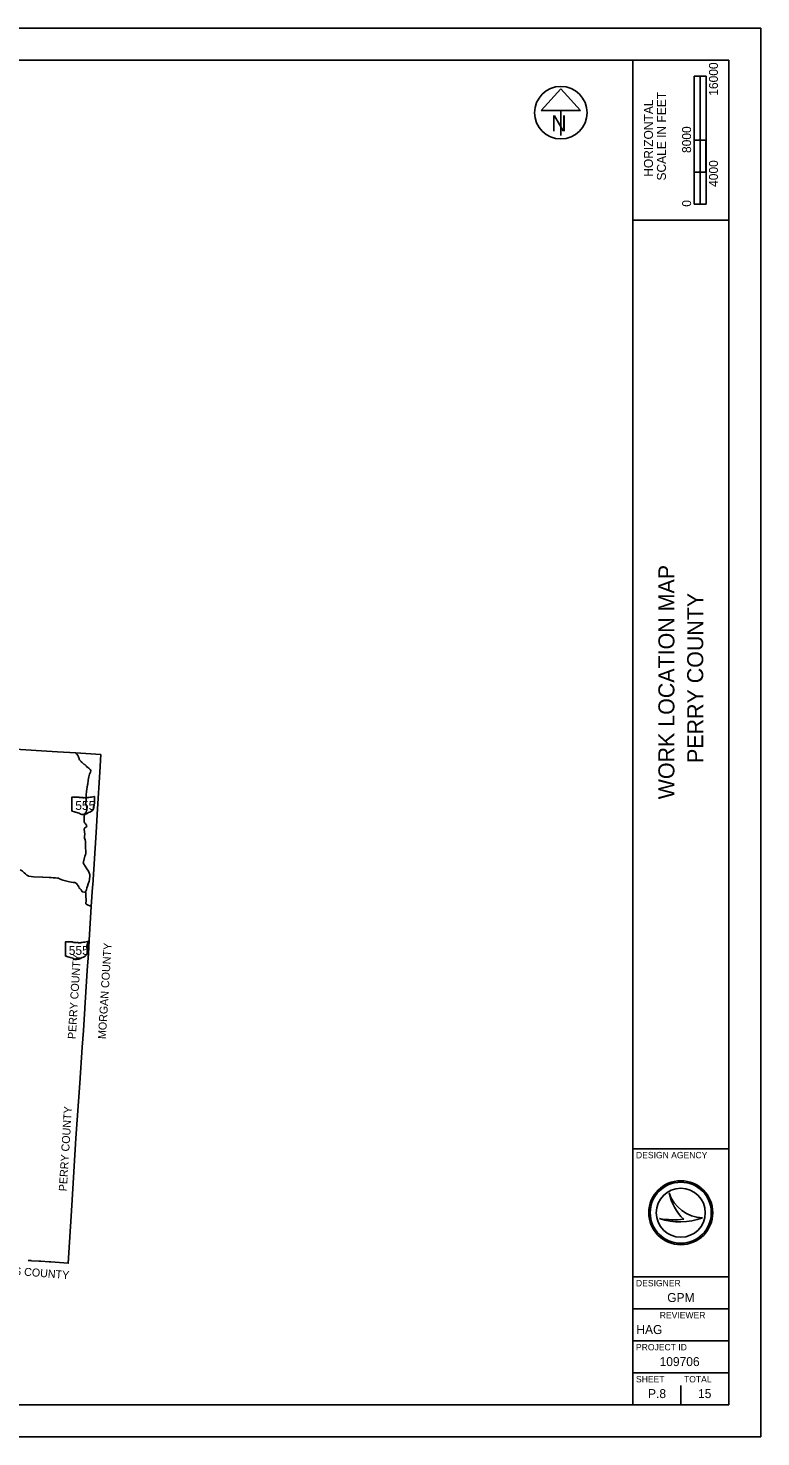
# Model space of a CAD drawing. Extents: x 1912787 to 2184787, y 543251 to 719251.
# Drawn here: x 2093246 to 2184787, y 543251 to 719251 of the extents above; entities that cross this region are included whole.
import ezdxf

# ---------------------------------------------------------------- set-up
doc = ezdxf.new("R2010")
doc.units = 0
for name, color, linetype in [('GM_X_County', 7, 'Continuous'), ('GM_X_County_Text', 7, 'Continuous'), ('GM_X_State_Location', 7, 'Continuous'), ('GM_X_State_Route', 7, 'Continuous'), ('GM_X_State_Shield', 7, 'Continuous'), ('SH_Border', 7, 'Continuous'), ('SH_Cut_Line', 7, 'Continuous'), ('SH_Data', 7, 'Continuous'), ('SH_Masking', 7, 'Continuous'), ('SH_Text', 7, 'Continuous')]:
    doc.layers.add(name, color=color, linetype=linetype)

msp = doc.modelspace()

# ---------------------------------------------------------------- linework, layer by layer
at = {"layer": 'GM_X_County'}
msp.add_lwpolyline([(2090938, 629224), (2096895, 628847), (2099187, 628710), (2102312, 628487), (2102193, 626283), (2101908, 621725), (2101721, 618763), (2101311, 612237), (2101290, 611908), (2101137, 609504), (2100881, 605294), (2100816, 604427), (2100776, 603648), (2100631, 601508), (2100343, 596816), (2100327, 596770), (2100147, 594037), (2099987, 591925), (2099681, 587430), (2099218, 580571), (2098707, 572170), (2098250, 564948), (2096075, 565106), (2095873, 565126), (2094827, 565192), (2094797, 565200), (2094779, 565204), (2094764, 565207), (2094750, 565209), (2094740, 565211), (2094727, 565212), (2094716, 565212), (2094701, 565213), (2094683, 565212), (2094668, 565211), (2094648, 565210), (2094631, 565207), (2094613, 565204), (2093651, 565260), (2093610, 565267), (2093571, 565272), (2093538, 565275), (2093505, 565278), (2093473, 565281), (2093444, 565283), (2093421, 565284), (2093383, 565286), (2093357, 565287), (2093335, 565287), (2093279, 565284), (2093242, 565282)], dxfattribs=at)
at = {"layer": 'GM_X_State_Route'}
for points in [[(2099600, 627994), (2099570, 628077), (2099522, 628214), (2099451, 628392), (2099374, 628518), (2099298, 628605), (2099188, 628707)], [(2101076, 626465), (2101081, 626479), (2101088, 626513), (2100994, 626609), (2100806, 626799), (2100700, 626898), (2100545, 626998), (2100502, 627052), (2100472, 627100), (2100453, 627131), (2100427, 627169), (2100408, 627187), (2100370, 627213), (2100312, 627242), (2100254, 627266), (2100196, 627297), (2100151, 627330), (2100111, 627364), (2099976, 627498), (2099922, 627559), (2099883, 627610), (2099831, 627677), (2099793, 627720), (2099748, 627765), (2099661, 627851), (2099626, 627921), (2099600, 627994)], [(2100572, 621814), (2100571, 621851), (2100568, 621979), (2100564, 622050), (2100492, 622189), (2100433, 622306), (2100418, 622362), (2100421, 622417), (2100438, 622470), (2100450, 622524), (2100481, 622839), (2100512, 623284), (2100512, 623462), (2100543, 623875), (2100669, 624702), (2100686, 624812), (2100760, 625292), (2100818, 625708), (2100851, 625884), (2100904, 626052), (2101021, 626309), (2101076, 626465)], [(2100227, 620259), (2100227, 620264), (2100229, 620349), (2100237, 620530), (2100238, 620563), (2100243, 620639), (2100243, 620701), (2100248, 620763), (2100256, 620821), (2100264, 620861), (2100289, 620950), (2100298, 620979), (2100310, 621008), (2100324, 621040), (2100336, 621063), (2100346, 621082), (2100374, 621129), (2100438, 621236), (2100484, 621313), (2100499, 621347), (2100508, 621372), (2100524, 621411), (2100538, 621450), (2100548, 621475), (2100552, 621492), (2100557, 621524), (2100560, 621544), (2100562, 621562), (2100566, 621601), (2100569, 621651), (2100569, 621699), (2100573, 621771), (2100572, 621814)], [(2100408, 611276), (2100464, 611414), (2100522, 611579), (2100591, 611844), (2100652, 612054), (2100742, 612343), (2100851, 612691), (2100894, 612858), (2100934, 613401), (2100932, 613525), (2100914, 613602), (2100870, 613699), (2100765, 613917), (2100585, 614226), (2100150, 614888), (2100131, 614961), (2100158, 615103), (2100330, 615799), (2100339, 615853), (2100350, 615895), (2100407, 616002), (2100438, 616062), (2100460, 616142), (2100427, 617136), (2100421, 617330), (2100428, 617496), (2100415, 617625), (2100354, 617832), (2100302, 618054), (2100274, 618180), (2100298, 618326), (2100309, 618521), (2100282, 618858), (2100241, 619116), (2100244, 619190), (2100271, 619254), (2100323, 619321), (2100558, 619494), (2100573, 619505), (2100586, 619514), (2100524, 619673), (2100407, 619847), (2100336, 619933), (2100281, 620014), (2100242, 620104), (2100237, 620123), (2100232, 620154), (2100228, 620186), (2100227, 620219), (2100227, 620259)], [(2092257, 614093), (2092407, 614019), (2092552, 613916), (2092757, 613724), (2092892, 613584), (2093069, 613433), (2093147, 613380), (2093234, 613338), (2093291, 613301), (2093344, 613282)], [(2093344, 613282), (2093921, 613233), (2095034, 613160)], [(2095034, 613160), (2095087, 613157), (2095851, 613117), (2096017, 613132), (2096109, 613128), (2096378, 613103), (2096525, 613096), (2096675, 613073), (2096929, 613058), (2097023, 613035), (2097154, 612983), (2097348, 612871), (2097595, 612783), (2098082, 612674), (2098421, 612602), (2098618, 612563), (2098871, 612516), (2099060, 612491), (2099171, 612457), (2099254, 612416), (2099326, 612338), (2099417, 612202), (2099470, 612148), (2099507, 612108), (2099565, 611968), (2099638, 611820), (2099691, 611762), (2099778, 611682), (2099849, 611607), (2099902, 611527), (2100011, 611349), (2100089, 611326), (2100275, 611300), (2100361, 611290), (2100408, 611276)], [(2100408, 611276), (2100432, 611248), (2100439, 611215), (2100444, 611101), (2100460, 610757), (2100484, 610316), (2100478, 610176), (2100465, 609961), (2100458, 609858), (2100465, 609825)], [(2100465, 609825), (2100485, 609797), (2100525, 609772), (2100578, 609761), (2100755, 609696), (2101138, 609501)], [(2100777, 603645), (2100702, 603918), (2100646, 604087), (2100602, 604252), (2100580, 604393), (2100579, 604512), (2100581, 604585), (2100597, 604681), (2100628, 604766), (2100667, 604862), (2100719, 604962), (2100882, 605291)]]:
    msp.add_lwpolyline(points, dxfattribs=at)
at = {"layer": 'GM_X_State_Shield'}
for p, q in [((2098713, 623153), (2098713, 621452)), ((2099561, 623182), (2098741, 623182)), ((2101515, 622334), (2101515, 623224)), ((2101515, 622334), (2101515, 622334)), ((2097900, 605048), (2097900, 603347)), ((2098748, 605077), (2097927, 605077)), ((2100701, 604230), (2100701, 605119)), ((2100701, 604230), (2100701, 604230))]:
    msp.add_line(p, q, dxfattribs=at)
for centre, major_axis, start_param, end_param in [((2098745, 623156), (32.5, 0), 1.7126934, 3.2834897), ((2099757, 623380), (315, 0), 4.042523, 4.731795), ((2099861, 622227), (1130, 0), 1.4047578, 1.6578581), ((2100118, 623165), (90.8, 0), 3.8360951, 5.1854146), ((2100251, 622969), (189, 0), 0.950623, 2.079405), ((2100495, 623238), (227, 0), 4.0815608, 5.1457227), ((2100896, 622662), (598, 0), 1.6990114, 2.1078141), ((2100517, 625501), (2971, 0), 4.8143942, 5.0423688), ((2101484, 623228), (31.2, 0), 6.1411519, 7.9890352), ((2098746, 621448), (32.7, 0), 3.00124, 4.5083009), ((2098751, 621622), (250, 0), 4.6659457, 4.8974612), ((2098802, 621353), (90.1, 0), 0.5192072, 1.6278991), ((2099939, 622882), (2146, 0), 4.1959971, 4.4889607), ((2100997, 620974), (407, 0), 1.6476453, 2.4884337), ((2100684, 621849), (743, 0), 5.1017525, 6.4400178), ((2101627, 621962), (211, 0), 2.3877238, 3.2625369), ((2101508, 622269), (48.3, 0), 1.8839779, 3.6710726), ((2101201, 622156), (290, 0), 5.9346948, 6.6959481), ((2101482, 622331), (33.4, 0), 5.05454, 6.4181714), ((2099300, 620687), (671, 0), 0.8235189, 1.3235874), ((2100026, 621345), (426, 0), 4.0264811, 4.9967352), ((2100272, 620757), (350, 0), 1.495662, 1.9409797), ((2100303, 621218), (227, 0), 4.6910439, 5.5073738), ((2100508, 621053), (63.9, 0), 1.1475842, 2.3151517), ((2100481, 621287), (240, 0), 4.9370686, 5.64225), ((2097932, 605052), (32.5, 0), 1.7126934, 3.2834897), ((2098943, 605275), (315, 0), 4.042523, 4.731795), ((2099047, 604122), (1130, 0), 1.4047578, 1.6578581), ((2099304, 605060), (90.8, 0), 3.8360951, 5.1854146), ((2099437, 604864), (189, 0), 0.950623, 2.079405), ((2099681, 605134), (227, 0), 4.0815608, 5.1457227), ((2100082, 604558), (598, 0), 1.6990114, 2.1078141), ((2099703, 607397), (2971, 0), 4.8143942, 5.0423688), ((2099870, 603744), (743, 0), 5.1017525, 6.4400178), ((2100813, 603857), (211, 0), 2.3877238, 3.2625369), ((2100694, 604164), (48.3, 0), 1.8839779, 3.6710726), ((2100387, 604052), (290, 0), 5.9346948, 6.6959481), ((2100670, 605123), (31.2, 0), 6.1411519, 7.9890352), ((2100668, 604226), (33.4, 0), 5.05454, 6.4181714), ((2097932, 603343), (32.7, 0), 3.00124, 4.5083009), ((2097937, 603517), (250, 0), 4.6659457, 4.8974612), ((2097988, 603249), (90.1, 0), 0.5192072, 1.6278991), ((2099126, 604777), (2146, 0), 4.1959971, 4.4889607), ((2098486, 602583), (671, 0), 0.8235189, 1.3235874), ((2099212, 603240), (426, 0), 4.0264811, 4.9967352), ((2099458, 602652), (350, 0), 1.495662, 1.9409797), ((2099489, 603113), (227, 0), 4.6910439, 5.5073738), ((2099695, 602948), (63.9, 0), 1.1475842, 2.3151517), ((2099667, 603182), (240, 0), 4.9370686, 5.64225), ((2100183, 602869), (407, 0), 1.6476453, 2.4884337)]:
    msp.add_ellipse(centre, major_axis=major_axis, ratio=0.8, start_param=start_param, end_param=end_param, dxfattribs=at)
at = {"layer": 'SH_Border'}
for p, q in [((2168787, 547251), (2168787, 715251)), ((2168787, 695251), (2180787, 695251)), ((2168787, 579251), (2180787, 579251)), ((2168787, 563251), (2180787, 563251)), ((2168787, 559251), (2180787, 559251)), ((2168787, 555251), (2180787, 555251)), ((2168787, 551251), (2180787, 551251))]:
    msp.add_line(p, q, dxfattribs=at)
msp.add_lwpolyline([(1924787, 715251), (2180787, 715251), (2180787, 547251), (1924787, 547251)], close=True, dxfattribs=at)
at = {"layer": 'SH_Cut_Line'}
msp.add_lwpolyline([(1912787, 543251), (2184787, 543251), (2184787, 719251), (1912787, 719251)], close=True, dxfattribs=at)
at = {"layer": 'SH_Data'}
for p, q in [((2176440, 697251), (2176440, 713251)), ((2177940, 713251), (2176440, 713251)), ((2176440, 705251), (2176440, 713251)), ((2176440, 713251), (2177187, 713251)), ((2177187, 713251), (2177193, 713251)), ((2177193, 713251), (2177193, 705251)), ((2177940, 713251), (2177940, 697251)), ((2177193, 705251), (2176440, 705251)), ((2177933, 705251), (2177187, 705251)), ((2177187, 705251), (2177187, 701251)), ((2177933, 701251), (2177933, 705251)), ((2177187, 701251), (2176440, 701251)), ((2176440, 701251), (2176440, 697251)), ((2177187, 697251), (2177187, 701251)), ((2177187, 701251), (2177933, 701251)), ((2177940, 697251), (2176440, 697251)), ((2176440, 697251), (2177187, 697251)), ((2173326, 573727), (2173326, 573727)), ((2172124, 570527), (2172124, 570527)), ((2174787, 571251), (2174787, 571251)), ((2177485, 570599), (2177485, 570599)), ((2174787, 547251), (2174787, 549651)), ((2171787, 548651), (2171787, 548651))]:
    msp.add_line(p, q, dxfattribs=at)
for radius in [4000, 3814, 3814, 3058]:
    msp.add_circle((2174787, 571251), radius, dxfattribs=at)
for centre, radius, start, end in [((2177714, 575232), 4639, 198.92567, 198.93195), ((2179560, 575011), 6365, 191.63793, 191.64215), ((2177714, 575232), 4639, 198.93195, 267.16574), ((2179560, 575011), 6365, 191.64215, 226.09467), ((2173971, 580486), 10128, 259.49639, 259.49952), ((2174702, 578211), 8105, 251.45274, 251.45764), ((2174702, 578211), 8105, 251.45764, 290.08324), ((2173971, 580486), 10128, 259.49952, 276.66723)]:
    msp.add_arc(centre, radius, start, end, dxfattribs=at)
at = {"layer": 'SH_Masking'}
msp.add_circle((2159798, 708690), 3280, dxfattribs=at)
at = {"layer": 'SH_Text'}
for p, q in [((2159798, 711680), (2157337, 708950)), ((2162259, 708950), (2159798, 711680)), ((2157337, 708950), (2162259, 708950)), ((2159798, 708950), (2159798, 705856))]:
    msp.add_line(p, q, dxfattribs=at)
msp.add_circle((2159798, 708690), 3280, dxfattribs=at)

# ---------------------------------------------------------------- texts
at = {"layer": 'GM_X_County_Text'}
for s, rotation, p in [('MORGAN COUNTY', 86.46062, (2102945, 592922)), ('PERRY COUNTY', 86.46062, (2099187, 592922)), ('PERRY COUNTY', 86.41019, (2098062, 573907)), ('ATHENS COUNTY', 355.51231, (2086932, 563846))]:
    msp.add_text(s, height=1000, rotation=rotation, dxfattribs=at).set_placement(p)
at = {"layer": 'GM_X_State_Location'}
for p in [(2100056, 622307), (2100777, 607246), (2100228, 604293)]:
    msp.add_text('555', height=1, rotation=0.00001, dxfattribs=at).set_placement(p)
for s, p in [('s', (2100409, 622380)), ('r', (2100409, 622380)), ('s', (2101130, 607319)), ('r', (2101130, 607319)), ('s', (2100581, 604366)), ('r', (2100581, 604366))]:
    msp.add_text(s, height=1, dxfattribs=at).set_placement(p)
at = {"layer": 'GM_X_State_Shield'}
for p in [(2099131, 621572), (2098317, 603467)]:
    msp.add_text('555', height=1120.7, dxfattribs=at).set_placement(p)
at = {"layer": 'SH_Data'}
for s, height, p in [('16000', 1120, (2179429, 710810)), ('SCALE IN FEET', 1120, (2172927, 700216)), ('HORIZONTAL', 1120, (2171307, 700685)), ('8000', 1120, (2176071, 703656)), ('4000', 1120, (2179429, 699419)), ('0', 1120, (2176071, 696941)), ('WORK LOCATION MAP', 2000, (2173987, 622909)), ('PERRY COUNTY', 2000, (2177587, 627447))]:
    msp.add_text(s, height=height, rotation=90, dxfattribs=at).set_placement(p)
for s, height, p in [('DESIGN AGENCY', 800, (2169187, 578051)), ('DESIGNER', 800, (2169187, 562051)), ('GPM', 1120, (2173094, 560091)), ('REVIEWER', 800, (2172161, 558051)), ('HAG', 1120, (2169240, 556091)), ('PROJECT ID', 800, (2169187, 554051)), ('109706', 1120, (2172140, 552091)), ('SHEET', 800, (2169187, 550051)), ('P.8', 1120, (2170697, 548091)), ('TOTAL', 800, (2175187, 550051)), ('15', 1120, (2176944, 548091))]:
    msp.add_text(s, height=height, dxfattribs=at).set_placement(p)
at = {"layer": 'SH_Text'}
msp.add_text('N', height=2000, dxfattribs=at).set_placement((2158588, 706359))

doc.saveas('drawing.dxf')
